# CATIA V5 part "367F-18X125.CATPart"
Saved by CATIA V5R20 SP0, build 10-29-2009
Part number: 367F-18X125
Definition: NONE
Nomenclature: 367F-18X125
Source: Unknown
Description: 367F-18X125
Bounding box of the stored display mesh (mm): x 0 to 125, y -14 to 14, z -14 to 14
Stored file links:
  C:\Users\Utente\Desktop\IO LAVORO\3D X SITO CF\X SITO\PLASTICA\3D files 367\367F-18X125.CATPart
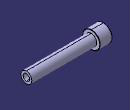
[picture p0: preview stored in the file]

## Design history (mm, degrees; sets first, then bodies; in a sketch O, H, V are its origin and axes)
Body1 "367F-18X125" (main body)
  Solid1: solid without history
